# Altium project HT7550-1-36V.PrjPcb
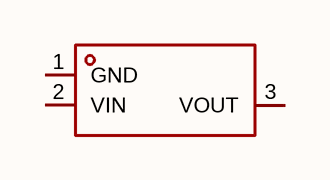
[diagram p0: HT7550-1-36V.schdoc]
1 sheet, 1 parts. Net scope: global (net labels, ports and power ports of the same name join across sheets).

## Sheet HT7550-1-36V.schdoc
size 127 x 101 mm

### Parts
U?  ht7550-1-36v  [SOT-89-3_L4.3-W2.3-P1.50-LS4.3-BR]  (value not drawn)

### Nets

Not connected (* = marked no-connect by the designer): U? 1(GND) 2(VIN) 3(VOUT)

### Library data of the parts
U? = ht7550-1-36v: 输出极性:正极;工作电压:35V;输出电压:5V;输出电流:150mA;电源纹波抑制比(PSRR):60dB@(1kHz);输出类型:固定;; Manufacturer: TECH PUBLIC(台舟); AddInBom: yes; ModelId: 13a61ebef0f84f538eafb98eafc62ef6; ModelTransform: 161.22,177.165,0,0,0,0,-13.11,0,0; Output Configuration: 正极; Voltage - Supply: 35V; Output Voltage: 5V; Output Current: 150mA; Voltage Dropout: 460mV@(100mA); standby current: 3uA; Output Type: 固定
